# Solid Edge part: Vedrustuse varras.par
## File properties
Author: Türk
Template: Iso Part.par
Last saved by: Türk
Revision: 9
Application: Solid Edge
Accuracy: 0,990
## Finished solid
Body 1: solid body, 39 faces, 102 edges, 62 vertices.
  Faces by surface: plane 29, cylinder 6, cone 4
  Edges by curve: line 70, circle 20, intersection 12
Bounding box of the edges (mm): 50.000 x 179.350 x 50.000, from (-25, -25, -25) to (25, 154.35, 25).
Cylindrical faces by radius (mm): R10.5 x3, R20 x2, R25 x1
Conical faces (half-angle, radius in mm at the cone's reference point): 45 deg R25 x4
Planar faces by outward normal: +x 3, +y 3, +z 6, -x 3, -y 2, -z 6, oblique 6
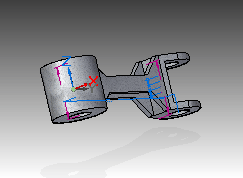
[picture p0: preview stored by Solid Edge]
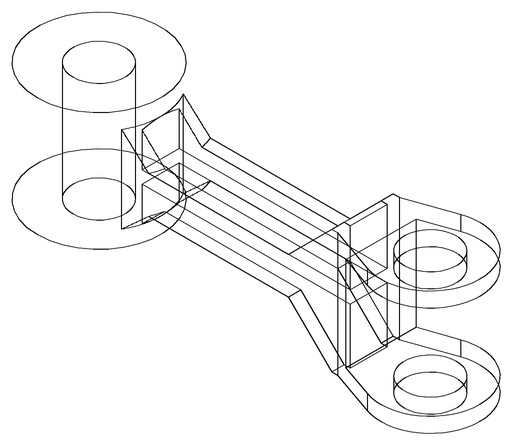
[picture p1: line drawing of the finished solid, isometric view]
